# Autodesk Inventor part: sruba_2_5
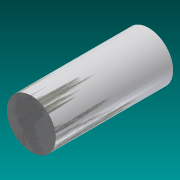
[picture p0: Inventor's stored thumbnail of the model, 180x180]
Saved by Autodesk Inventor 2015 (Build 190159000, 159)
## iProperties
Created: 2016-02
Part Number: sruba_2_5
Material: Generic
Document SubType Name: Modeling
Designer: Rafał
Density: 1 g/cm^3
Appearance: Aluminum - Polished
Author: Rafał
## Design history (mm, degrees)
sketch "Sketch1"
  geometry: C1 r 1.25 at (0, 0); 1 further point
  constraints: 1 centre point, 1 coincident
  dimensions: "d0" = 2.5 diameter of C1
extrude "Extrusion1" new body sketch "Sketch1" distance "d1" = 6; taper "d2" = 0 deg
body "Solid1"
